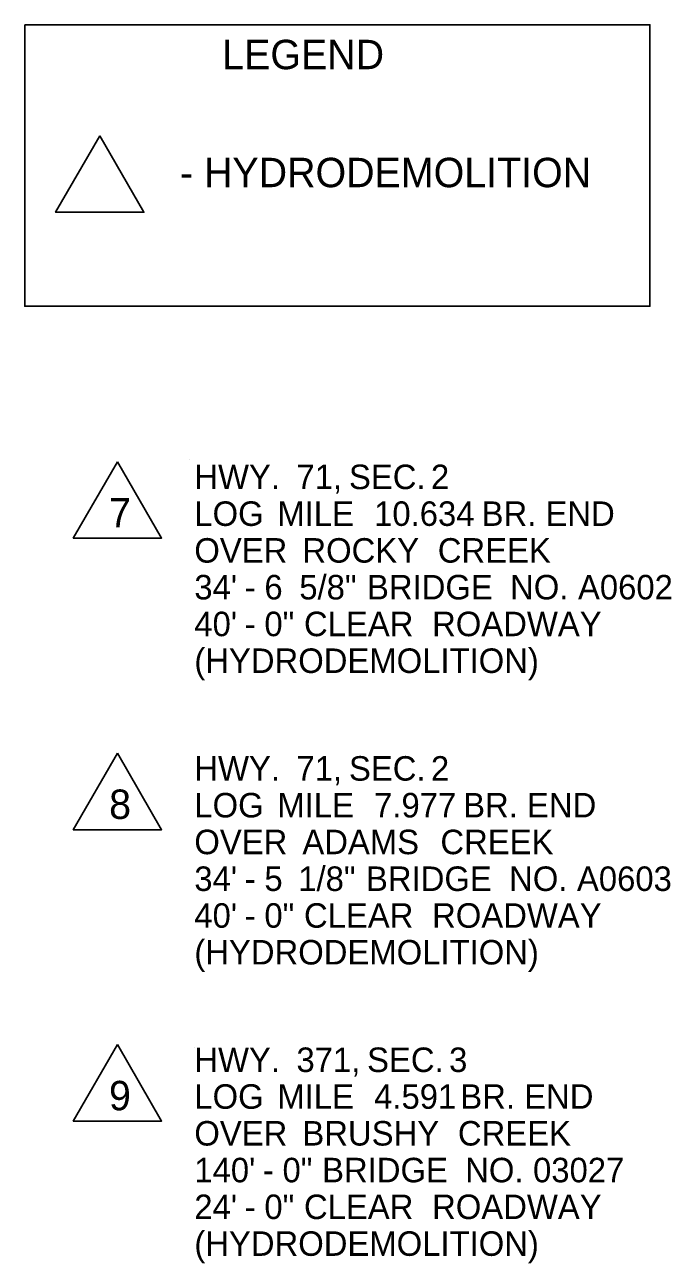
# Model space of a CAD drawing. Extents: x -17742 to 32032, y -17264 to 5867.
# Drawn here: x 1934 to 3910, y -2307 to 1483 of the extents above; entities that cross this region are included whole.
import ezdxf

# ---------------------------------------------------------------- set-up
doc = ezdxf.new("R2010")
doc.units = 0
doc.layers.add('Default', color=7, linetype='Continuous')
doc.layers.add('R_Annotation', color=7, linetype='Continuous')

msp = doc.modelspace()

# ---------------------------------------------------------------- linework, layer by layer
at = {"layer": 'R_Annotation'}
for p, q in [((2437.8, 151.7), (2437.8, 151.7)), ((2452.5, -1646.9), (2452.5, -1646.9))]:
    msp.add_line(p, q, dxfattribs=at)
for points in [[(1934.3, 1482.6), (3844.9, 1482.6), (3844.9, 621.4), (1934.3, 621.4)], [(2163.6, 1142.8), (2298.6, 909), (2028.6, 909)], [(2217.5, 145.5), (2352.5, -88.3), (2082.5, -88.3)], [(2217.5, -746.6), (2352.5, -980.4), (2082.5, -980.4)], [(2217.5, -1638.1), (2352.5, -1871.9), (2082.5, -1871.9)]]:
    msp.add_lwpolyline(points, close=True, dxfattribs=at)

# ---------------------------------------------------------------- texts
at = {"layer": 'Default'}
for s, p in [('HWY.', (2452.5, 61.7)), (' 71,', (2736.8, 61.7)), (' SEC.', (2897.3, 61.7)), (' 2', (3147.9, 61.7)), ('LOG', (2452.5, -50.8)), (' MILE', (2678.4, -50.8)), (' 10.634', (2974.2, -50.8)), (' BR.', (3302.8, -50.8)), (' END', (3498, -50.8)), ('OVER', (2452.5, -163.3)), (' ROCKY', (2754.9, -163.3)), (' CREEK', (3168.7, -163.3)), ("34'", (2452.5, -275.8)), (' 6', (2638.8, -275.8)), ('  5/8"', (2717.6, -275.8)), (' BRIDGE', (2952.5, -275.8)), (' NO.', (3389.8, -275.8)), (' A0602', (3597.3, -275.8)), (' -', (2578.6, -275.8)), ("40'", (2452.5, -388.3)), (' 0"', (2638.8, -388.3)), (' CLEAR', (2759.8, -388.3)), (' ROADWAY', (3151.4, -388.3)), (' -', (2578.6, -388.3)), ('(HYDRODEMOLITION)', (2452.5, -500.8)), ('HWY.', (2452.5, -830.4)), (' 71,', (2736.8, -830.4)), (' SEC.', (2897.3, -830.4)), (' 2', (3147.9, -830.4)), ('LOG', (2452.5, -942.9)), (' MILE', (2678.4, -942.9)), (' 7.977', (2974.2, -942.9)), (' BR.', (3246.3, -942.9)), (' END', (3441.5, -942.9)), ('OVER', (2452.5, -1055.4)), (' ADAMS', (2754.9, -1055.4)), (' CREEK', (3176.8, -1055.4)), ("34'", (2452.5, -1167.9)), (' 5', (2638.8, -1167.9)), ('  1/8"', (2714.5, -1167.9)), (' BRIDGE', (2949.4, -1167.9)), (' NO.', (3386.8, -1167.9)), (' A0603', (3594.2, -1167.9)), (' -', (2578.6, -1167.9)), ("40'", (2452.5, -1280.4)), (' 0"', (2638.8, -1280.4)), (' CLEAR', (2759.8, -1280.4)), (' ROADWAY', (3151.4, -1280.4)), (' -', (2578.6, -1280.4)), ('(HYDRODEMOLITION)', (2452.5, -1392.9)), ('HWY.', (2452.5, -1721.9)), (' 371,', (2736.8, -1721.9)), (' SEC.', (2952.7, -1721.9)), (' 3', (3203.3, -1721.9)), ('LOG', (2452.5, -1834.4)), (' MILE', (2678.4, -1834.4)), (' 4.591', (2974.2, -1834.4)), (' BR.', (3237.6, -1834.4)), (' END', (3432.9, -1834.4)), ('OVER', (2452.5, -1946.9)), (' BRUSHY', (2754.9, -1946.9)), (' CREEK', (3230.3, -1946.9)), ("140'", (2452.5, -2059.4)), (' 0"', (2694.2, -2059.4)), (' BRIDGE', (2815.2, -2059.4)), (' NO.', (3252.5, -2059.4)), (' 03027', (3460, -2059.4)), (' -', (2634, -2059.4)), ("24'", (2452.5, -2171.9)), (' 0"', (2638.8, -2171.9)), (' CLEAR', (2759.8, -2171.9)), (' ROADWAY', (3151.4, -2171.9)), (' -', (2578.6, -2171.9)), ('(HYDRODEMOLITION)', (2452.5, -2284.4))]:
    msp.add_text(s, height=75, dxfattribs=at).set_placement(p)
at = {"layer": 'R_Annotation'}
for s, p in [('LEGEND', (2537.6, 1346.7)), ('- HYDRODEMOLITION', (2408.4, 985.6)), ('7', (2192, -55.4)), ('8', (2192, -947.5)), ('9', (2191.6, -1839))]:
    msp.add_text(s, height=90, dxfattribs=at).set_placement(p)

doc.saveas('drawing.dxf')
